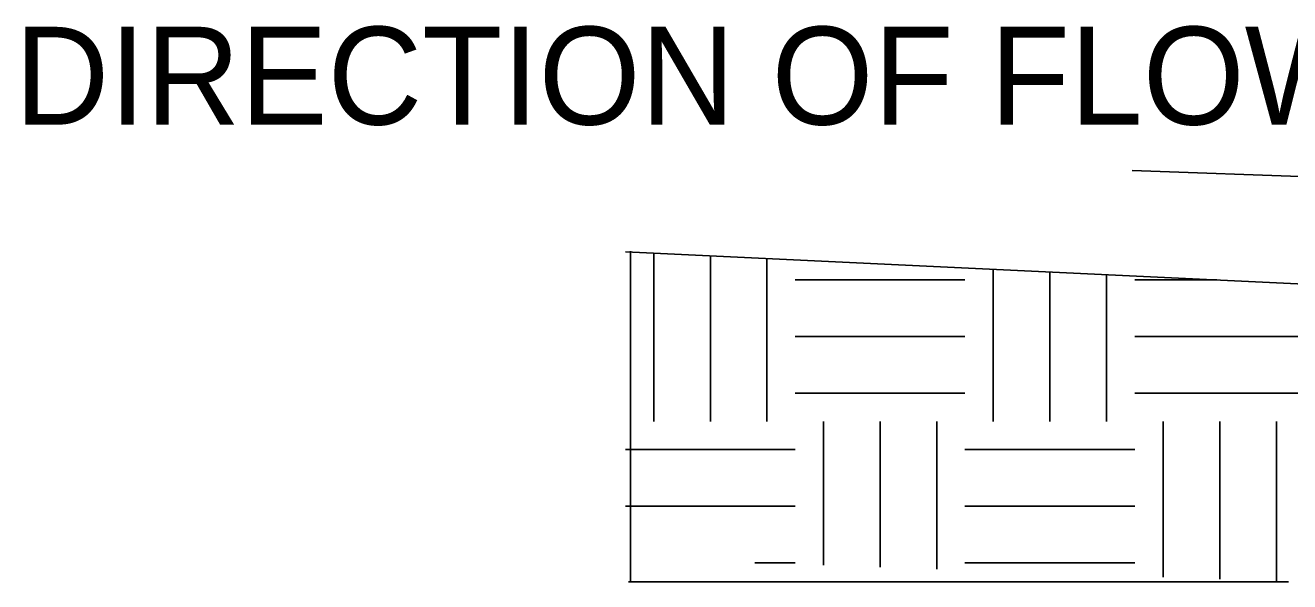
# Model space of a CAD drawing. Extents: x 0 to 2.83, y -0.06 to 1.83.
# Drawn here: x 1.8111 to 1.924, y 0.391 to 0.4407 of the extents above; entities that cross this region are included whole.
import ezdxf

# ---------------------------------------------------------------- set-up
doc = ezdxf.new("R2010")
doc.units = 0
for name, color, linetype in [('Edge_of_Truck_Apron', 7, 'Continuous'), ('Existing Grade', 7, 'Continuous'), ('Existing Soil', 7, 'Continuous'), ('Longitudinal Joint', 7, 'Continuous')]:
    doc.layers.add(name, color=color, linetype=linetype)

msp = doc.modelspace()

# ---------------------------------------------------------------- linework, layer by layer
at = {"layer": 'Existing Grade'}
msp.add_line((2.01208, 0.41342), (1.86466, 0.42048), dxfattribs=at)
at = {"layer": 'Existing Soil'}
for p, q in [((1.86511, 0.42054), (1.86511, 0.39104)), ((1.86719, 0.42036), (1.86719, 0.40531)), ((1.87225, 0.42011), (1.87225, 0.40531)), ((1.8773, 0.41987), (1.8773, 0.40531)), ((1.89499, 0.41795), (1.87983, 0.41795)), ((1.89499, 0.41795), (1.87983, 0.41795)), ((1.89499, 0.41289), (1.87983, 0.41289)), ((1.89499, 0.41289), (1.87983, 0.41289)), ((1.92533, 0.41289), (1.91016, 0.41289)), ((1.92533, 0.41289), (1.91016, 0.41289)), ((1.89499, 0.40784), (1.87983, 0.40784)), ((1.89499, 0.40784), (1.87983, 0.40784)), ((1.92533, 0.40784), (1.91016, 0.40784)), ((1.92533, 0.40784), (1.91016, 0.40784)), ((1.88236, 0.39246), (1.88236, 0.40531)), ((1.88236, 0.39246), (1.88236, 0.40531)), ((1.88741, 0.39228), (1.88741, 0.40531)), ((1.88741, 0.39228), (1.88741, 0.40531)), ((1.89247, 0.3921), (1.89247, 0.40531)), ((1.89247, 0.3921), (1.89247, 0.40531)), ((1.91269, 0.39138), (1.91269, 0.40531)), ((1.91269, 0.39138), (1.91269, 0.40531)), ((1.91774, 0.3912), (1.91774, 0.40531)), ((1.91774, 0.3912), (1.91774, 0.40531)), ((1.9228, 0.39102), (1.9228, 0.40531)), ((1.9228, 0.39102), (1.9228, 0.40531)), ((1.86466, 0.40278), (1.87983, 0.40278)), ((1.86466, 0.40278), (1.87983, 0.40278)), ((1.89499, 0.40278), (1.91016, 0.40278)), ((1.89499, 0.40278), (1.91016, 0.40278)), ((1.86466, 0.39773), (1.87983, 0.39773)), ((1.86466, 0.39773), (1.87983, 0.39773)), ((1.89499, 0.39773), (1.91016, 0.39773)), ((1.89499, 0.39773), (1.91016, 0.39773)), ((1.87623, 0.39267), (1.87983, 0.39267)), ((1.87623, 0.39267), (1.87983, 0.39267)), ((1.89499, 0.39267), (1.91016, 0.39267)), ((1.89499, 0.39267), (1.91016, 0.39267)), ((1.86495, 0.39097), (1.92387, 0.39097))]:
    msp.add_line(p, q, dxfattribs=at)
at = {"layer": 'Longitudinal Joint'}
for p, q in [((1.90993, 0.42775), (1.93851, 0.42668)), ((1.90993, 0.42775), (1.93851, 0.42668)), ((2.01208, 0.41342), (1.86466, 0.42048)), ((1.86719, 0.42036), (1.86719, 0.40531)), ((1.87225, 0.42011), (1.87225, 0.40531)), ((1.8773, 0.41987), (1.8773, 0.40531)), ((1.89752, 0.41891), (1.89752, 0.40531)), ((1.89752, 0.41891), (1.89752, 0.40531)), ((1.90258, 0.41866), (1.90258, 0.40531)), ((1.90258, 0.41866), (1.90258, 0.40531)), ((1.90763, 0.41842), (1.90763, 0.40531)), ((1.90763, 0.41842), (1.90763, 0.40531)), ((1.91747, 0.41795), (1.91016, 0.41795)), ((1.91747, 0.41795), (1.91016, 0.41795))]:
    msp.add_line(p, q, dxfattribs=at)

# ---------------------------------------------------------------- texts
at = {"layer": 'Edge_of_Truck_Apron'}
msp.add_text('DIRECTION OF FLOW', height=0.00875, dxfattribs=at).set_placement((1.81011, 0.43184))

doc.saveas('drawing.dxf')
